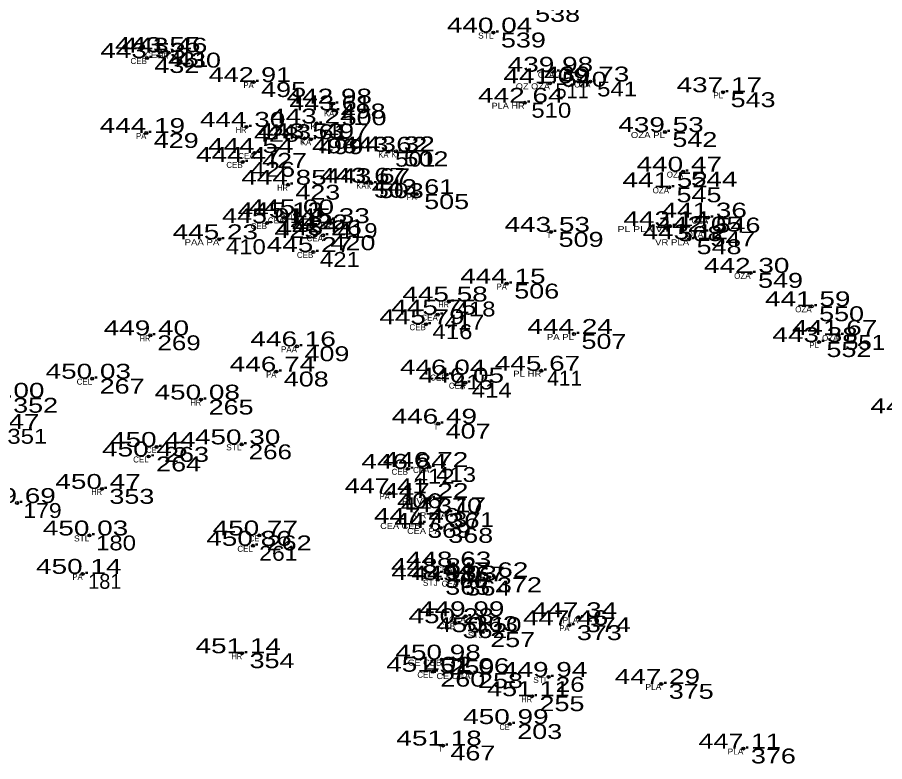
# Model space of a CAD drawing. Extents: x -639390 to -639074, y -1138747 to -1138358.
# Drawn here: x -639201.57 to -639157.96, y -1138697.01 to -1138659.59 of the extents above; entities that cross this region are included whole.
import ezdxf
from ezdxf.enums import TextEntityAlignment as Align

# ---------------------------------------------------------------- set-up
doc = ezdxf.new("R2010")
doc.units = 0
doc.header["$LTSCALE"] = 0.3
doc.header["$PDMODE"] = 32
doc.header["$PDSIZE"] = 0.15
for name, color, linetype in [('11', 7, 'Continuous'), ('12', 7, 'Continuous'), ('13', 7, 'Continuous'), ('57', 7, 'Continuous')]:
    doc.layers.add(name, color=color, linetype=linetype)

msp = doc.modelspace()

# ---------------------------------------------------------------- linework, layer by layer
at = {"layer": '11'}
for p in [(-639177.63, -1138660.36), (-639195.06, -1138661.64), (-639194.32, -1138661.34), (-639193.97, -1138661.37), (-639174.57, -1138662.33), (-639189.69, -1138662.85), (-639174.79, -1138662.91), (-639172.75, -1138662.82), (-639166.08, -1138663.36), (-639176.06, -1138663.89), (-639185.69, -1138663.93), (-639185.64, -1138664.27), (-639190.05, -1138665.1), (-639186.52, -1138664.93), (-639195.09, -1138665.41), (-639169.01, -1138665.36), (-639187.13, -1138665.68), (-639186.8, -1138665.72), (-639189.64, -1138666.41), (-639182.91, -1138666.35), (-639182.53, -1138666.33), (-639190.24, -1138666.86), (-639168.09, -1138667.35), (-639187.97, -1138668.01), (-639184.02, -1138667.91), (-639183.77, -1138667.93), (-639168.8, -1138668.14), (-639181.49, -1138668.48), (-639187.6, -1138669.5), (-639189.02, -1138669.94), (-639188.15, -1138669.65), (-639185.8, -1138669.94), (-639166.84, -1138669.66), (-639174.73, -1138670.38), (-639168.75, -1138670.09), (-639167.09, -1138670.36), (-639191.42, -1138670.75), (-639186.2, -1138670.55), (-639167.79, -1138670.75), (-639186.69, -1138671.39), (-639164.7, -1138672.44), (-639176.96, -1138672.98), (-639179.87, -1138673.88), (-639161.63, -1138674.12), (-639180.43, -1138674.54), (-639181.03, -1138675.02), (-639194.89, -1138675.58), (-639173.58, -1138675.51), (-639160.28, -1138675.56), (-639187.51, -1138676.13), (-639161.26, -1138675.92), (-639188.55, -1138677.4), (-639175.22, -1138677.36), (-639197.81, -1138677.76), (-639179.99, -1138677.55), (-639179.05, -1138677.96), (-639192.33, -1138678.81), (-639180.41, -1138680.02), (-639194.57, -1138681.19), (-639190.3, -1138681.06), (-639194.97, -1138681.67), (-639180.85, -1138682.2), (-639181.93, -1138682.29), (-639197.32, -1138683.3), (-639182.85, -1138683.52), (-639180.84, -1138683.76), (-639201.59, -1138684.01), (-639179.96, -1138684.47), (-639181.3, -1138685.01), (-639180.28, -1138685.26), (-639197.95, -1138685.64), (-639189.41, -1138685.64), (-639189.73, -1138686.16), (-639179.69, -1138687.2), (-639198.29, -1138687.57), (-639180.44, -1138687.53), (-639180.43, -1138687.87), (-639179.41, -1138687.91), (-639177.83, -1138687.74), (-639179.56, -1138690.05), (-639179.03, -1138689.7), (-639173.36, -1138689.75), (-639178.17, -1138690.5), (-639173.81, -1138690.15), (-639190.27, -1138691.56), (-639180.22, -1138691.88), (-639180.68, -1138692.49), (-639178.78, -1138692.56), (-639174.86, -1138692.75), (-639169.19, -1138693.1), (-639175.69, -1138693.72), (-639176.81, -1138695.12), (-639180.17, -1138696.2), (-639165.06, -1138696.35)]:
    msp.add_point(p, dxfattribs=at)

# ---------------------------------------------------------------- texts
at = {"layer": '12'}
for s, width, p in [('440.04 ', 1.4, (-639177.63, -1138660.36)), ('443.55 ', 1.4, (-639194.32, -1138661.34)), ('443.46 ', 1.4, (-639193.969, -1138661.37)), ('443.53 ', 1.4, (-639195.06, -1138661.64)), ('439.98 ', 1.4, (-639174.57, -1138662.33)), ('442.91 ', 1.35, (-639189.689, -1138662.85)), ('439.73 ', 1.4, (-639172.75, -1138662.82)), ('441.09 ', 1.4, (-639174.79, -1138662.91)), ('437.17 ', 1.4, (-639166.08, -1138663.36)), ('442.98 ', 1.4, (-639185.69, -1138663.93)), ('442.64 ', 1.4, (-639176.06, -1138663.89)), ('443.61 ', 1.35, (-639185.639, -1138664.27)), ('443.24 ', 1.4, (-639186.52, -1138664.93)), ('444.19 ', 1.4, (-639195.09, -1138665.41)), ('444.30 ', 1.4, (-639190.05, -1138665.1)), ('439.53 ', 1.4, (-639169.01, -1138665.36)), ('443.53 ', 1.4, (-639187.13, -1138665.68)), ('443.61 ', 1.35, (-639186.799, -1138665.72)), ('443.62 ', 1.4, (-639182.91, -1138666.35)), ('443.32 ', 1.4, (-639182.53, -1138666.33)), ('444.54 ', 1.4, (-639189.64, -1138666.41)), ('444.47 ', 1.4, (-639190.24, -1138666.86)), ('440.47 ', 1.4, (-639168.09, -1138667.35)), ('444.85 ', 1.4, (-639187.97, -1138668.01)), ('443.67 ', 1.4, (-639184.02, -1138667.91)), ('443.67 ', 1.4, (-639183.77, -1138667.93)), ('443.61 ', 1.35, (-639181.489, -1138668.48)), ('441.52 ', 1.4, (-639168.8, -1138668.14)), ('445.13 ', 1.4, (-639188.15, -1138669.65)), ('445.00 ', 1.4, (-639187.6, -1138669.5)), ('441.36 ', 1.4, (-639166.839, -1138669.66)), ('445.01 ', 1.35, (-639189.019, -1138669.94)), ('445.33 ', 1.4, (-639185.8, -1138669.94)), ('443.14 ', 1.4, (-639168.75, -1138670.09)), ('445.26 ', 1.4, (-639186.199, -1138670.55)), ('443.53 ', 1.4, (-639174.73, -1138670.38)), ('442.05 ', 1.4, (-639167.09, -1138670.36)), ('445.23 ', 1.4, (-639191.42, -1138670.75)), ('443.12 ', 1.4, (-639167.79, -1138670.75)), ('445.27 ', 1.4, (-639186.69, -1138671.39)), ('442.30 ', 1.4, (-639164.7, -1138672.44)), ('444.15 ', 1.4, (-639176.96, -1138672.98)), ('445.58 ', 1.4, (-639179.87, -1138673.88)), ('441.59 ', 1.4, (-639161.63, -1138674.12)), ('445.75 ', 1.4, (-639180.43, -1138674.54)), ('445.79 ', 1.4, (-639181.03, -1138675.02)), ('444.24 ', 1.4, (-639173.58, -1138675.51)), ('449.40 ', 1.4, (-639194.89, -1138675.58)), ('443.38 ', 1.4, (-639161.26, -1138675.92)), ('441.67 ', 1.4, (-639160.28, -1138675.56)), ('446.16 ', 1.4, (-639187.509, -1138676.13)), ('446.74 ', 1.4, (-639188.55, -1138677.4)), ('446.04 ', 1.4, (-639179.99, -1138677.55)), ('445.67 ', 1.4, (-639175.22, -1138677.36)), ('450.03 ', 1.4, (-639197.81, -1138677.76)), ('446.05 ', 1.4, (-639179.05, -1138677.96)), ('450.00 ', 1.4, (-639202.16, -1138678.72)), ('450.08 ', 1.4, (-639192.33, -1138678.81)), ('442.52 ', 1.4, (-639156.33, -1138679.5)), ('449.47 ', 1.4, (-639202.41, -1138680.28)), ('446.49 ', 1.4, (-639180.41, -1138680.02)), ('450.30 ', 1.4, (-639190.3, -1138681.06)), ('450.44 ', 1.4, (-639194.57, -1138681.19)), ('450.45 ', 1.4, (-639194.97, -1138681.67)), ('446.84 ', 1.4, (-639181.93, -1138682.29)), ('446.72 ', 1.4, (-639180.85, -1138682.2)), ('450.47 ', 1.4, (-639197.32, -1138683.3)), ('447.41 ', 1.35, (-639182.849, -1138683.52)), ('447.22 ', 1.4, (-639180.84, -1138683.76)), ('449.69 ', 1.4, (-639201.59, -1138684.01)), ('447.17 ', 1.4, (-639179.96, -1138684.47)), ('447.46 ', 1.4, (-639181.299, -1138685.01)), ('447.36 ', 1.4, (-639180.279, -1138685.26)), ('450.03 ', 1.4, (-639197.95, -1138685.64)), ('450.77 ', 1.4, (-639189.41, -1138685.64)), ('450.86 ', 1.4, (-639189.729, -1138686.16)), ('448.63 ', 1.4, (-639179.69, -1138687.2)), ('450.14 ', 1.4, (-639198.29, -1138687.57)), ('448.83 ', 1.4, (-639180.44, -1138687.53)), ('448.98 ', 1.4, (-639180.43, -1138687.87)), ('449.03 ', 1.4, (-639179.41, -1138687.91)), ('447.62 ', 1.4, (-639177.83, -1138687.74)), ('449.99 ', 1.4, (-639179.03, -1138689.7)), ('447.34 ', 1.4, (-639173.36, -1138689.75)), ('450.28 ', 1.4, (-639179.56, -1138690.05)), ('447.46 ', 1.4, (-639173.809, -1138690.15)), ('450.10 ', 1.4, (-639178.17, -1138690.5)), ('451.14 ', 1.4, (-639190.27, -1138691.56)), ('450.98 ', 1.4, (-639180.22, -1138691.88)), ('451.02 ', 1.4, (-639180.68, -1138692.49)), ('451.06 ', 1.4, (-639178.779, -1138692.56)), ('449.94 ', 1.4, (-639174.86, -1138692.75)), ('447.29 ', 1.4, (-639169.19, -1138693.1)), ('451.11 ', 1.35, (-639175.689, -1138693.72)), ('450.99 ', 1.4, (-639176.81, -1138695.12)), ('451.18 ', 1.4, (-639180.17, -1138696.2)), ('447.11 ', 1.35, (-639165.059, -1138696.35))]:
    msp.add_text(s, height=0.75, dxfattribs=dict(at, width=width)).set_placement(p, align=Align.CENTER)
at = {"layer": '13'}
for s, width, p in [(' 538', 1.35, (-639175.91, -1138659.82)), (' 539', 1.35, (-639177.63, -1138661.11)), (' 432', 1.35, (-639195.06, -1138662.39)), (' 431', 1.2, (-639194.32, -1138662.09)), (' 430', 1.35, (-639193.97, -1138662.12)), (' 540', 1.35, (-639174.57, -1138663.08)), (' 495', 1.35, (-639189.69, -1138663.6)), (' 541', 1.2, (-639172.75, -1138663.57)), (' 543', 1.35, (-639166.08, -1138664.11)), (' 498', 1.35, (-639185.69, -1138664.68)), (' 500', 1.35, (-639185.64, -1138665.02)), (' 510', 1.2, (-639176.06, -1138664.64)), (' 428', 1.35, (-639190.05, -1138665.85)), (' 497', 1.35, (-639186.52, -1138665.68)), (' 429', 1.35, (-639195.09, -1138666.16)), (' 542', 1.35, (-639169.01, -1138666.11)), (' 496', 1.35, (-639187.13, -1138666.43)), (' 499', 1.35, (-639186.8, -1138666.47)), (' 427', 1.35, (-639189.64, -1138667.16)), (' 501', 1.2, (-639182.91, -1138667.1)), (' 502', 1.35, (-639182.53, -1138667.08)), (' 426', 1.35, (-639190.24, -1138667.61)), (' 544', 1.4, (-639168.09, -1138668.1)), (' 423', 1.35, (-639187.97, -1138668.76)), (' 504', 1.35, (-639184.02, -1138668.66)), (' 503', 1.35, (-639183.77, -1138668.68)), (' 545', 1.35, (-639168.8, -1138668.89)), (' 505', 1.35, (-639181.49, -1138669.23)), (' 422', 1.35, (-639187.6, -1138670.25)), (' 425', 1.35, (-639189.02, -1138670.69)), (' 424', 1.4, (-639188.15, -1138670.4)), (' 419', 1.2, (-639185.8, -1138670.69)), (' 546', 1.35, (-639166.84, -1138670.41)), (' 509', 1.35, (-639174.73, -1138671.13)), (' 508', 1.35, (-639168.75, -1138670.84)), (' 547', 1.35, (-639167.09, -1138671.11)), (' 410', 1.2, (-639191.42, -1138671.5)), (' 420', 1.35, (-639186.2, -1138671.3)), (' 548', 1.35, (-639167.79, -1138671.5)), (' 421', 1.2, (-639186.69, -1138672.14)), (' 549', 1.35, (-639164.7, -1138673.19)), (' 506', 1.35, (-639176.96, -1138673.73)), (' 418', 1.2, (-639179.87, -1138674.63)), (' 550', 1.35, (-639161.63, -1138674.87)), (' 417', 1.2, (-639180.43, -1138675.29)), (' 416', 1.2, (-639181.03, -1138675.77)), (' 269', 1.3, (-639194.89, -1138676.33)), (' 507', 1.35, (-639173.58, -1138676.26)), (' 551', 1.2, (-639160.28, -1138676.31)), (' 552', 1.35, (-639161.26, -1138676.67)), (' 409', 1.35, (-639187.51, -1138676.88)), (' 411', 1.05, (-639175.22, -1138678.11)), (' 267', 1.35, (-639197.81, -1138678.51)), (' 408', 1.35, (-639188.55, -1138678.15)), (' 415', 1.2, (-639179.99, -1138678.3)), (' 414', 1.2, (-639179.05, -1138678.71)), (' 352', 1.35, (-639202.16, -1138679.47)), (' 265', 1.35, (-639192.33, -1138679.56)), (' 351', 1.2, (-639202.41, -1138681.03)), (' 407', 1.35, (-639180.41, -1138680.77)), (' 263', 1.35, (-639194.57, -1138681.94)), (' 266', 1.3, (-639190.3, -1138681.81)), (' 264', 1.35, (-639194.97, -1138682.42)), (' 412', 1.2, (-639181.93, -1138683.04)), (' 413', 1.2, (-639180.85, -1138682.95)), (' 353', 1.35, (-639197.32, -1138684.05)), (' 406', 1.35, (-639182.85, -1138684.27)), (' 370', 1.35, (-639180.84, -1138684.51)), (' 179', 1.15, (-639201.59, -1138684.76)), (' 371', 1.2, (-639179.96, -1138685.22)), (' 369', 1.3, (-639181.3, -1138685.76)), (' 180', 1.2, (-639197.95, -1138686.39)), (' 262', 1.35, (-639189.41, -1138686.39)), (' 368', 1.35, (-639180.28, -1138686.01)), (' 261', 1.15, (-639189.73, -1138686.91)), (' 367', 1.35, (-639179.69, -1138687.95)), (' 366', 1.3, (-639180.44, -1138688.28)), (' 372', 1.35, (-639177.83, -1138688.49)), (' 365', 1.35, (-639180.43, -1138688.62)), (' 364', 1.35, (-639179.41, -1138688.66)), (' 363', 1.35, (-639179.03, -1138690.45)), (' 374', 1.35, (-639173.36, -1138690.5)), (' 362', 1.35, (-639179.56, -1138690.8)), (' 373', 1.35, (-639173.81, -1138690.9)), (' 257', 1.35, (-639178.17, -1138691.25)), (' 354', 1.35, (-639190.27, -1138692.31)), (' 259', 1.35, (-639180.22, -1138692.63)), (' 260', 1.35, (-639180.68, -1138693.24)), (' 258', 1.35, (-639178.78, -1138693.31)), (' 26', 1.3, (-639174.86, -1138693.5)), (' 375', 1.35, (-639169.19, -1138693.85)), (' 255', 1.35, (-639175.69, -1138694.47)), (' 203', 1.35, (-639176.81, -1138695.87)), (' 467', 1.35, (-639180.17, -1138696.95)), (' 376', 1.35, (-639165.06, -1138697.1))]:
    msp.add_text(s, height=0.75, dxfattribs=dict(at, width=width)).set_placement(p)
for s, p in [(' 511', (-639174.79, -1138663.66)), (' 181', (-639198.29, -1138688.32))]:
    msp.add_text(s, height=0.75, dxfattribs=at).set_placement(p)
at = {"layer": '57'}
for s, width, p in [('STL', 1.05, (-639177.629, -1138660.66)), ('HR', 0.85, (-639193.969, -1138661.67)), ('PA', 0.95, (-639189.69, -1138663.15)), ('OZ OZA', 1.15, (-639174.79, -1138663.21)), ('KA', 0.95, (-639185.64, -1138664.57)), ('K', 0.65, (-639185.689, -1138664.23)), ('PLA HR', 1.15, (-639176.059, -1138664.19)), ('HR', 0.85, (-639190.049, -1138665.4)), ('PA K', 1.2, (-639186.519, -1138665.23)), ('PA', 0.95, (-639195.09, -1138665.71)), ('OZA PL', 1.2, (-639169.009, -1138665.66)), ('K', 0.65, (-639187.129, -1138665.98)), ('KA', 0.95, (-639186.8, -1138666.02)), ('KA', 0.95, (-639182.91, -1138666.65)), ('K', 0.65, (-639182.529, -1138666.63)), ('HR', 0.85, (-639187.969, -1138668.31)), ('KA', 0.95, (-639184.02, -1138668.21)), ('K', 0.65, (-639183.769, -1138668.23)), ('PA', 0.95, (-639181.49, -1138668.78)), ('STL', 1.05, (-639187.599, -1138669.8)), ('HR', 0.85, (-639185.799, -1138670.24)), ('T', 0.85, (-639174.73, -1138670.68)), ('PL PLA VR', 1.3, (-639168.749, -1138670.39)), ('PAA PA', 1.2, (-639191.42, -1138671.05)), ('VR PLA', 1.2, (-639167.79, -1138671.05)), ('PA', 0.95, (-639176.96, -1138673.28)), ('HR', 0.85, (-639179.869, -1138674.18)), ('HR', 0.85, (-639194.889, -1138675.88)), ('PA PL', 1.2, (-639173.579, -1138675.81)), ('PL HR', 1.2, (-639175.219, -1138677.66)), ('PA', 0.95, (-639188.55, -1138677.7)), ('HR', 0.85, (-639192.329, -1138679.11)), ('T', 0.85, (-639180.41, -1138680.32)), ('CE', 0.9, (-639194.57, -1138681.49)), ('STL', 1.05, (-639190.299, -1138681.36)), ('HR', 0.85, (-639197.319, -1138683.6)), ('PA', 0.95, (-639182.85, -1138683.82)), ('PL VR', 1.2, (-639180.839, -1138684.06)), ('VR PLA', 1.2, (-639179.96, -1138684.77)), ('CEA CEB', 1.15, (-639181.299, -1138685.31)), ('STL', 1.05, (-639197.949, -1138685.94)), ('CE', 0.9, (-639189.41, -1138685.94)), ('CEA PA', 1.15, (-639180.28, -1138685.56)), ('PA', 0.95, (-639198.29, -1138687.87)), ('PA', 0.95, (-639177.83, -1138688.04)), ('STJ', 1.05, (-639180.43, -1138688.17)), ('PLA', 1.05, (-639173.36, -1138690.05)), ('PA', 0.95, (-639173.81, -1138690.45)), ('STJ', 1.05, (-639178.17, -1138690.8)), ('HR', 0.85, (-639190.269, -1138691.86)), ('CE CEB', 1.15, (-639180.219, -1138692.18)), ('CE CEA', 1.15, (-639178.78, -1138692.86)), ('STL', 1.05, (-639174.859, -1138693.05)), ('PLA', 1.05, (-639169.19, -1138693.4)), ('HR', 0.85, (-639175.689, -1138694.02)), ('CE', 0.9, (-639176.81, -1138695.42)), ('T', 0.85, (-639180.17, -1138696.5)), ('PLA', 1.05, (-639165.06, -1138696.65))]:
    msp.add_text(s, height=0.3, dxfattribs=dict(at, width=width)).set_placement(p, align=Align.RIGHT)
for s, p in [('CEB', (-639195.059, -1138661.94)), ('CEA', (-639194.32, -1138661.64)), ('OZA', (-639174.57, -1138662.63)), ('OZA', (-639172.75, -1138663.12)), ('PL', (-639166.079, -1138663.66)), ('CEA', (-639189.64, -1138666.71)), ('CEB', (-639190.239, -1138667.16)), ('OZA', (-639168.09, -1138667.65)), ('OZA', (-639168.8, -1138668.44)), ('CEB', (-639189.019, -1138670.24)), ('CEA', (-639188.15, -1138669.95)), ('OZA', (-639166.84, -1138669.96)), ('OZA', (-639167.09, -1138670.66)), ('CEA', (-639186.2, -1138670.85)), ('CEB', (-639186.689, -1138671.69)), ('OZA', (-639164.7, -1138672.74)), ('OZA', (-639161.63, -1138674.42)), ('CEA', (-639180.43, -1138674.84)), ('CEB', (-639181.029, -1138675.32)), ('OZA', (-639160.28, -1138675.86)), ('PL', (-639161.259, -1138676.22)), ('PAA', (-639187.51, -1138676.43)), ('CEL', (-639197.809, -1138678.06)), ('CEB', (-639179.989, -1138677.85)), ('CEA', (-639179.05, -1138678.26)), ('CEL', (-639194.969, -1138681.97)), ('CEB', (-639181.929, -1138682.59)), ('CEA', (-639180.85, -1138682.5)), ('CEL', (-639189.729, -1138686.46)), ('CEA', (-639179.69, -1138687.5)), ('CEB', (-639180.439, -1138687.83)), ('CEA', (-639179.41, -1138688.21)), ('CEA', (-639179.03, -1138690)), ('CEB', (-639179.559, -1138690.35)), ('CEL', (-639180.679, -1138692.79))]:
    msp.add_text(s, height=0.3, dxfattribs=at).set_placement(p, align=Align.RIGHT)

doc.saveas('drawing.dxf')
